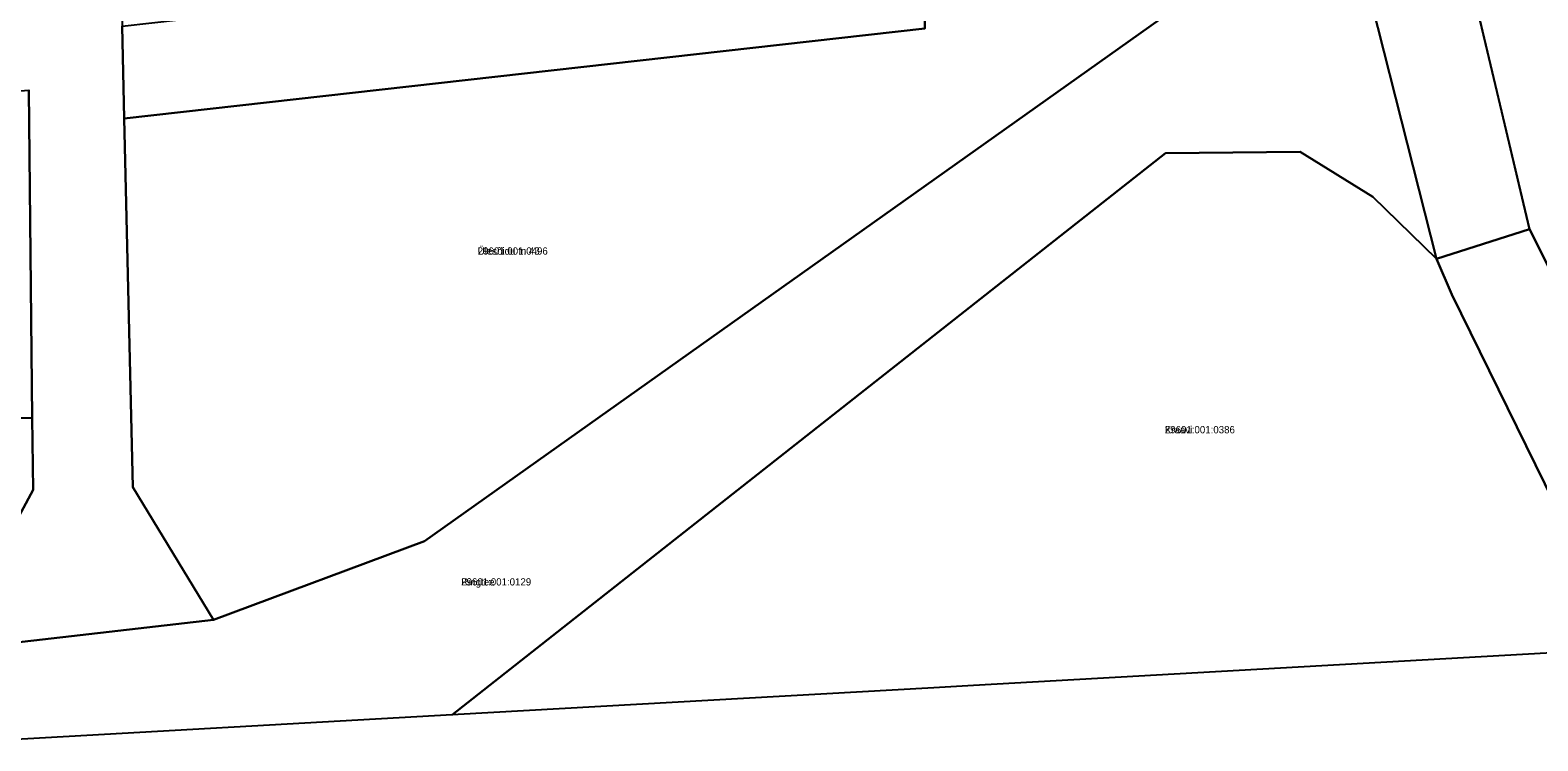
# Model space of a CAD drawing. Extents: x 518839 to 525192, y 6573164 to 6576561.
# Drawn here: x 524240.2 to 524552.3, y 6573427.3 to 6573574.3 of the extents above; entities that cross this region are included whole.
import ezdxf

# ---------------------------------------------------------------- set-up
doc = ezdxf.new("R2010")
doc.units = 0
for name, color, linetype in [('L_AADRESS', 7, 'Continuous'), ('PIIR', 7, 'Continuous'), ('TUNNUS', 7, 'Continuous')]:
    doc.layers.add(name, color=color, linetype=linetype)

msp = doc.modelspace()

# ---------------------------------------------------------------- linework, layer by layer
at = {"layer": 'PIIR'}
for points in [[(524248.4, 6573876.78), (524250.25, 6573836.78), (524249.61, 6573815.83), (524250.51, 6573794.86), (524250.95, 6573773.98), (524251.33, 6573751.84), (524256.24, 6573751.93), (524256.23, 6573737.6), (524251.56, 6573737.38), (524252.91, 6573688.82), (524256.48, 6573674.06), (524256.96, 6573672.11), (524257.57, 6573646.62), (524258.38, 6573613), (524259.25, 6573575.13), (524259.66, 6573556.05), (524261.43, 6573479.78), (524278.19, 6573452.33), (524222.92, 6573446.04), (524240.81, 6573479.26), (524240.63, 6573494.16), (524239.93, 6573561.93)], [(524735.02, 6573622.76), (524723.6, 6573620.44), (524538.31, 6573584.92), (524550.61, 6573533.15), (524531.32, 6573527.03), (524511.92, 6573603.47), (524511.93, 6573641.51), (524511.96, 6573677.83), (524511.99, 6573694.36), (524519.02, 6573750.89), (524525.67, 6573786.48), (524510.13, 6573796.53), (524516.82, 6573801.58), (524522.7, 6573803.05), (524528.6, 6573801.93), (524529.53, 6573806.84), (524529.17, 6573817.64), (524533.84, 6573836.07), (524542.18, 6573861.09), (524547.46, 6573876.94)], [(524761.11, 6573457.07), (524598.59, 6573447.96), (524572.8, 6573488.89), (524550.61, 6573533.15), (524544.23, 6573560.02), (524538.31, 6573584.92), (524723.6, 6573620.44), (524735.02, 6573622.76)], [(524222.92, 6573446.04), (524278.19, 6573452.33), (524321.87, 6573468.64), (524511.92, 6573603.47), (524531.32, 6573527.03), (524518.18, 6573539.88), (524503.14, 6573549.18), (524475.23, 6573548.91), (524327.54, 6573432.69), (524232.37, 6573427.33)]]:
    msp.add_lwpolyline(points, dxfattribs=at)
for points in [[(524261.43, 6573479.78), (524259.66, 6573556.05), (524425.44, 6573574.71), (524425.42, 6573593.78), (524450.05, 6573596.53), (524511.92, 6573603.47), (524321.87, 6573468.64), (524278.19, 6573452.33)], [(524259.66, 6573556.05), (524259.25, 6573575.13), (524289.97, 6573578.59), (524317.43, 6573581.67), (524333.44, 6573583.45), (524369.43, 6573587.5), (524409.43, 6573592), (524425.42, 6573593.78), (524425.44, 6573574.71)], [(524207.63, 6573559.48), (524239.93, 6573561.93), (524240.63, 6573494.16), (524212.56, 6573493.46)], [(524327.54, 6573432.69), (524475.23, 6573548.91), (524503.14, 6573549.18), (524518.18, 6573539.88), (524531.32, 6573527.03), (524534.5, 6573519.67), (524555.72, 6573476.55), (524571.14, 6573446.42), (524435.52, 6573438.78), (524427.25, 6573438.3)], [(524534.5, 6573519.67), (524531.32, 6573527.03), (524550.61, 6573533.15), (524572.8, 6573488.89), (524598.59, 6573447.96), (524571.14, 6573446.42), (524555.72, 6573476.55)], [(524135.9, 6573489.47), (524135.51, 6573491.38), (524164.28, 6573492.15), (524188.55, 6573492.71), (524212.56, 6573493.46), (524240.63, 6573494.16), (524240.81, 6573479.26), (524222.92, 6573446.04), (524155.35, 6573438.41), (524150.8, 6573437.86), (524149.35, 6573441.04), (524141.37, 6573467.23), (524141.04, 6573468.32), (524139.26, 6573474.13), (524138.11, 6573478.17), (524136.47, 6573486.56)]]:
    msp.add_lwpolyline(points, close=True, dxfattribs=at)

# ---------------------------------------------------------------- texts
at = {"layer": 'L_AADRESS'}
for s, p in [('Ülesõidu tn 43', (524332.86, 6573527.9)), ('Kraavi', (524475.1, 6573490.94)), ('Ringtee', (524329.43, 6573459.46))]:
    msp.add_text(s, height=1.5, dxfattribs=at).set_placement(p)
at = {"layer": 'TUNNUS'}
for s, p in [('29601:001:0496', (524332.86, 6573527.9)), ('29601:001:0386', (524475.1, 6573490.94)), ('29601:001:0129', (524329.43, 6573459.46))]:
    msp.add_text(s, height=1.5, dxfattribs=at).set_placement(p)

doc.saveas('drawing.dxf')
